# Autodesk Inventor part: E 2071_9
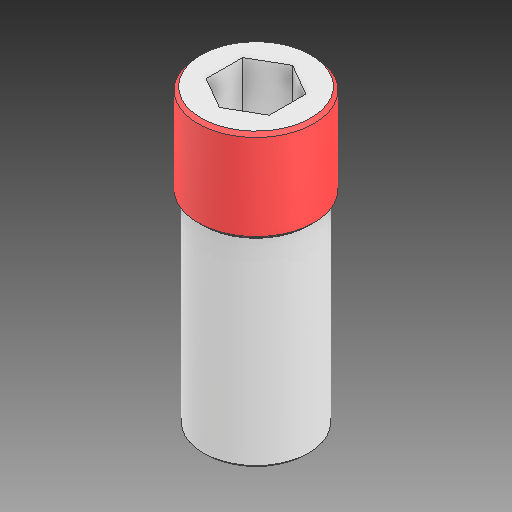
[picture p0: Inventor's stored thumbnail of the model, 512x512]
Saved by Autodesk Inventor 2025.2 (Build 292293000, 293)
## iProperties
Created: 2025-04
Part Number: E 2071_9
Material: Všeobecné
Document SubType Name: Modeling
Designer: Patrik
Density: 1 g/cm^3
Appearance: Výchozí
Mass: 15.5947 g
Surface Area: 50.4471 cm^2
Volume: 15.5947 cm^3
Author: Patrik
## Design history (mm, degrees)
feature "Base1"
node "Těleso1"
